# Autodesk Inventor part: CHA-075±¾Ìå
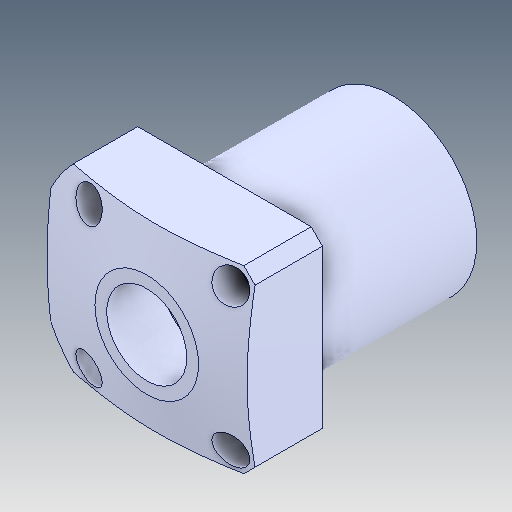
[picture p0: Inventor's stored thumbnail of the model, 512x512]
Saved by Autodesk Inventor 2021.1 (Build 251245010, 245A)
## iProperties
Created: 2021-05
Part Number: CHA-075±¾Ìå
Material: Ogólny
Document SubType Name: Modeling
Designer: user
Density: 1 g/cm^3
Appearance: Domyślna
Author: user
Revision Number: ÈÎºÎ
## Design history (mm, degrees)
feature "µ¹½Ç1"
node "Bryła1"
